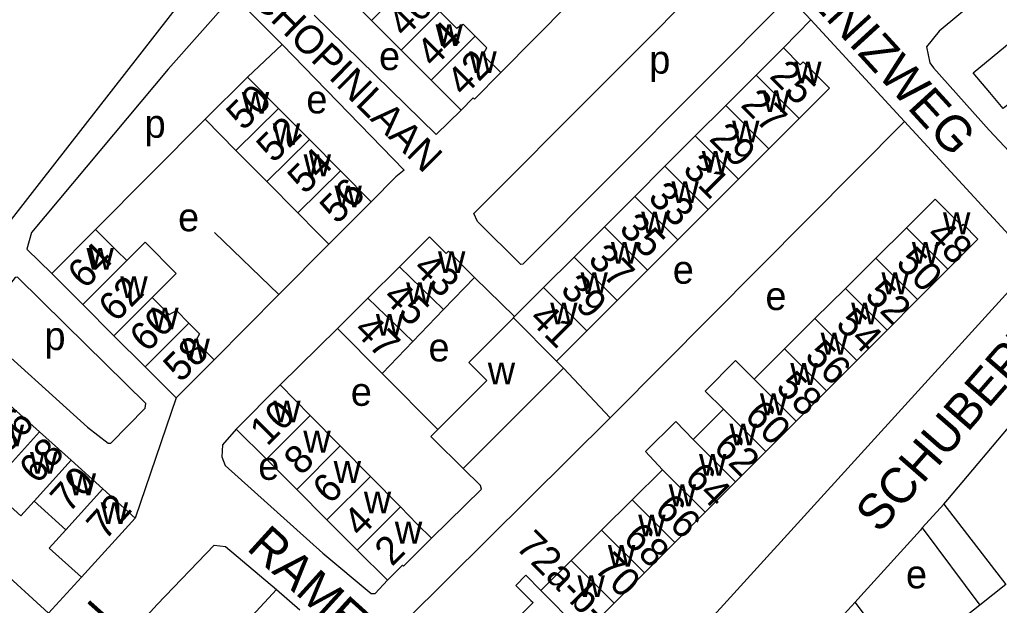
# Model space of a CAD drawing. Extents: x 159045 to 160918, y 380454 to 382516.
# Drawn here: x 159519.6 to 159658, y 381804.1 to 381886.8 of the extents above; entities that cross this region are included whole.
import ezdxf

# ---------------------------------------------------------------- set-up
doc = ezdxf.new("R2010")
doc.units = 0
for name, color, linetype in [('BLT_Basislijn', 7, 'Continuous'), ('BLT_Bebouwing', 7, 'Continuous'), ('BLT_Centroide', 7, 'Continuous'), ('BLT_Huisnummer', 7, 'Continuous'), ('BLT_Huisnummer_ tussenligend', 7, 'Continuous'), ('BLT_Huisnummer_reeks', 7, 'Continuous'), ('BLT_Onderverdeling_panden', 7, 'Continuous'), ('BLT_Straatnaam', 7, 'Continuous'), ('BLT_Straatnaam_verkleind', 7, 'Continuous')]:
    doc.layers.add(name, color=color, linetype=linetype)

msp = doc.modelspace()

# ---------------------------------------------------------------- linework, layer by layer
at = {"layer": 'BLT_Basislijn'}
for p, q in [((159631.34, 381886.81), (159628.29, 381890.11)), ((159587.58, 381879.35), (159597.19, 381889.05)), ((159627.48, 381882.85), (159631.34, 381886.81)), ((159644.57, 381872.44), (159631.34, 381886.81)), ((159556.7, 381883.3), (159551.82, 381878.71)), ((159545.83, 381872.77), (159530.37, 381857.19)), ((159556.25, 381848.03), (159547.18, 381856.77)), ((159556.25, 381848.03), (159563.28, 381855.14)), ((159583.86, 381850.43), (159589.52, 381844.89)), ((159547.1, 381838.78), (159556.25, 381848.03)), ((159556.44, 381835.24), (159564.51, 381843.2)), ((159596.45, 381837.61), (159603.01, 381830.59)), ((159570.83, 381836.86), (159578.69, 381828.95)), ((159541.75, 381833.42), (159535.95, 381816.45)), ((159647.09, 381815.05), (159650.13, 381818.42)), ((159650.13, 381818.42), (159658.86, 381807.04)), ((159647.09, 381815.05), (159655.21, 381804.14)), ((159513.46, 381812.35), (159523.74, 381802.99)), ((159528.39, 381808.1), (159523.74, 381802.99)), ((159555.91, 381806.36), (159559.19, 381803.48)), ((159637.61, 381804.56), (159634.52, 381801.16)), ((159644.4, 381795.56), (159637.61, 381804.56))]:
    msp.add_line(p, q, dxfattribs=at)
for points in [[(159671.87, 381915.68), (159677.46, 381909.03), (159676.79, 381907.98), (159673.6, 381905.32), (159649.48, 381885.21), (159647.67, 381882.98), (159648.15, 381880.73), (159648.65, 381880.03), (159656.52, 381871.2), (159665.8, 381861.36), (159667.35, 381860.48), (159668.8, 381860.27), (159671.09, 381861.15), (159710.49, 381901.86), (159730.69, 381922.64), (159732.46, 381924.74), (159732.71, 381927.22), (159731.89, 381928.43)], [(159531.44, 381910.25), (159541.64, 381900.41), (159542.72, 381899.11), (159542.72, 381889.82), (159522.41, 381863.71)], [(159628.29, 381890.11), (159590.71, 381852.28), (159590.42, 381852.23), (159584.27, 381858.32), (159583.75, 381859.44), (159619.87, 381895.69), (159620.88, 381896.42), (159622.32, 381896.52), (159628.29, 381890.11)], [(159556.7, 381883.3), (159550.19, 381889.89), (159549.56, 381889.98), (159540.63, 381879.85), (159521.32, 381856.75), (159520.65, 381854.44), (159524.17, 381850.99)], [(159581.97, 381874.07), (159578.45, 381870.61), (159561.21, 381887.45)], [(159556.7, 381883.3), (159573.94, 381865.59), (159572.75, 381864.63), (159569.29, 381861.09)], [(159644.57, 381872.44), (159660.96, 381854.63), (159661.66, 381853.63), (159661.82, 381852.68), (159661.18, 381850.54), (159599.18, 381782.35), (159598.21, 381781.87), (159596.31, 381781.68), (159595.12, 381782.25), (159574.14, 381801.25), (159574.2, 381802.01), (159603.01, 381830.59)], [(159603.01, 381830.59), (159603.52, 381831.1), (159644.57, 381872.44)], [(159522.41, 381863.71), (159472.38, 381799.37)], [(159526.08, 381843.82), (159519.34, 381850.45), (159519.02, 381850.4), (159513.78, 381843.71), (159513.9, 381843.1), (159529.21, 381829.29), (159532.16, 381827.01), (159532.54, 381827.01), (159537.36, 381831.96), (159537.45, 381832.64), (159526.08, 381843.82)], [(159650.13, 381818.42), (159650.71, 381819.07), (159660.55, 381830.73), (159662.87, 381831.27), (159663.98, 381831.15), (159676.84, 381819.54), (159684.1, 381812.42)], [(159550.22, 381829.02), (159548.3, 381826.78), (159548.2, 381825.08), (159548.68, 381823.88), (159562.44, 381811.5), (159569.26, 381805.8), (159569.83, 381805.78), (159571.59, 381807.65)], [(159577.79, 381813.58), (159584.85, 381820.51), (159584.73, 381821.06), (159582.28, 381823.44)], [(159647.09, 381815.05), (159646.82, 381814.74), (159638.42, 381805.46), (159637.61, 381804.56)], [(159512.29, 381774.89), (159539.04, 381804.23), (159547.11, 381812.6), (159548.72, 381812.44), (159555.91, 381806.36)], [(159555.91, 381806.36), (159520.46, 381767.98), (159519.92, 381768.08), (159515.83, 381771.39), (159512.29, 381774.89)]]:
    msp.add_lwpolyline(points, dxfattribs=at)
at = {"layer": 'BLT_Bebouwing'}
for p, q in [((159564.78, 381891.24), (159569.31, 381886.71)), ((159569.31, 381886.71), (159573.52, 381882.51)), ((159623.61, 381878.97), (159627.48, 381882.85)), ((159573.52, 381882.51), (159577.74, 381878.3)), ((159545.83, 381872.77), (159551.82, 381878.71)), ((159551.82, 381878.71), (159556.19, 381874.3)), ((159619.33, 381874.69), (159623.61, 381878.97)), ((159577.74, 381878.3), (159581.97, 381874.07)), ((159615.04, 381870.41), (159619.33, 381874.69)), ((159556.19, 381874.3), (159560.56, 381869.9)), ((159550.19, 381868.36), (159545.83, 381872.77)), ((159629.71, 381872.87), (159625.43, 381868.59)), ((159610.76, 381866.12), (159615.04, 381870.41)), ((159560.56, 381869.9), (159564.93, 381865.49)), ((159554.56, 381863.96), (159550.19, 381868.36)), ((159625.43, 381868.59), (159621.14, 381864.3)), ((159564.93, 381865.49), (159569.29, 381861.09)), ((159606.48, 381861.84), (159610.76, 381866.12)), ((159558.92, 381859.55), (159554.56, 381863.96)), ((159621.14, 381864.3), (159616.86, 381860.02)), ((159569.29, 381861.09), (159563.28, 381855.14)), ((159602.2, 381857.56), (159606.48, 381861.84)), ((159616.86, 381860.02), (159612.58, 381855.74)), ((159524.17, 381850.99), (159530.37, 381857.19)), ((159597.92, 381853.28), (159602.2, 381857.56)), ((159644.84, 381857.41), (159640.54, 381853.14)), ((159612.58, 381855.74), (159608.3, 381851.46)), ((159593.63, 381848.99), (159597.92, 381853.28)), ((159640.54, 381853.14), (159636.23, 381848.88)), ((159528.56, 381846.59), (159524.17, 381850.99)), ((159573.26, 381851.92), (159568.82, 381847.49)), ((159608.3, 381851.46), (159604.02, 381847.18)), ((159646.4, 381847.29), (159650.68, 381851.58)), ((159579.51, 381845.91), (159583.86, 381850.43)), ((159589.52, 381844.89), (159593.63, 381848.99)), ((159636.23, 381848.88), (159631.93, 381844.61)), ((159568.82, 381847.49), (159564.51, 381843.2)), ((159604.02, 381847.18), (159599.73, 381842.89)), ((159642.12, 381843), (159646.4, 381847.29)), ((159532.96, 381842.2), (159528.56, 381846.59)), ((159575.17, 381841.39), (159579.51, 381845.91)), ((159589.35, 381844.71), (159589.52, 381844.89)), ((159631.93, 381844.61), (159627.63, 381840.34)), ((159564.51, 381843.2), (159570.83, 381836.86)), ((159599.73, 381842.89), (159595.45, 381838.61)), ((159637.84, 381838.71), (159642.12, 381843)), ((159537.35, 381837.81), (159532.96, 381842.2)), ((159570.83, 381836.86), (159575.17, 381841.39)), ((159627.63, 381840.34), (159623.33, 381836.07)), ((159547.1, 381838.78), (159541.75, 381833.42)), ((159595.45, 381838.61), (159596.45, 381837.61)), ((159633.55, 381834.42), (159637.84, 381838.71)), ((159541.75, 381833.42), (159537.35, 381837.81)), ((159596.45, 381837.61), (159582.28, 381823.44)), ((159550.22, 381829.02), (159556.44, 381835.24)), ((159556.44, 381835.24), (159560.68, 381830.93)), ((159629.27, 381830.14), (159633.55, 381834.42)), ((159517.84, 381832.77), (159522.43, 381828.64)), ((159619.02, 381831.8), (159614.72, 381827.54)), ((159560.68, 381830.93), (159564.92, 381826.62)), ((159554.49, 381824.74), (159550.22, 381829.02)), ((159624.99, 381825.85), (159629.27, 381830.14)), ((159522.43, 381828.64), (159526.9, 381824.61)), ((159578.07, 381827.59), (159582.28, 381823.44)), ((159564.92, 381826.62), (159569.16, 381822.32)), ((159558.76, 381820.47), (159554.49, 381824.74)), ((159620.71, 381821.56), (159624.99, 381825.85)), ((159526.9, 381824.61), (159531.37, 381820.58)), ((159610.42, 381823.27), (159606.12, 381819)), ((159569.16, 381822.32), (159573.4, 381818.01)), ((159531.37, 381820.58), (159535.95, 381816.45)), ((159616.43, 381817.27), (159620.71, 381821.56)), ((159563.04, 381816.2), (159558.76, 381820.47)), ((159526.16, 381814.8), (159521.69, 381818.83)), ((159606.12, 381819), (159601.81, 381814.73)), ((159535.95, 381816.45), (159528.39, 381808.1)), ((159612.14, 381812.98), (159616.43, 381817.27)), ((159567.31, 381811.92), (159563.04, 381816.2)), ((159601.81, 381814.73), (159597.51, 381810.47)), ((159607.86, 381808.7), (159612.14, 381812.98)), ((159571.59, 381807.65), (159567.31, 381811.92)), ((159597.51, 381810.47), (159593.21, 381806.2)), ((159603.58, 381804.41), (159607.86, 381808.7)), ((159658.86, 381807.04), (159655.21, 381804.14)), ((159599.3, 381800.12), (159603.58, 381804.41)), ((159655.21, 381804.14), (159651.63, 381801.3))]:
    msp.add_line(p, q, dxfattribs=at)
for points in [[(159578.99, 381887.98), (159581.32, 381885.65), (159582.28, 381886.19), (159583.95, 381884.52)], [(159587.58, 381879.35), (159585.05, 381881.87), (159585.62, 381882.85), (159583.95, 381884.52)], [(159627.48, 381882.85), (159629.86, 381880.47), (159630.27, 381880.87), (159633.99, 381877.15), (159629.71, 381872.87)], [(159667.17, 381874.66), (159662.55, 381870.82), (159659.21, 381874.85), (159658.49, 381874.26), (159656.61, 381876.52), (159654.29, 381879.31), (159659.62, 381883.75), (159661.81, 381881.12)], [(159581.97, 381874.07), (159583.69, 381875.79), (159583.86, 381875.62), (159587.58, 381879.35)], [(159650.68, 381851.58), (159654.95, 381855.85), (159652.86, 381857.94), (159652.65, 381857.73), (159648.91, 381861.47), (159646.83, 381859.39), (159644.84, 381857.41)], [(159563.28, 381855.14), (159561.62, 381856.81), (159558.92, 381859.55)], [(159530.37, 381857.19), (159533.32, 381854.24), (159534.76, 381852.8)], [(159534.76, 381852.8), (159537.35, 381855.39), (159541.75, 381851), (159538.36, 381847.61)], [(159583.86, 381850.43), (159580.18, 381854.12), (159579.86, 381853.8), (159577.51, 381856.16), (159573.26, 381851.92)], [(159538.36, 381847.61), (159540.76, 381845.21), (159541.77, 381845.74), (159543.52, 381843.99)], [(159578.69, 381828.95), (159585.62, 381835.88), (159583.07, 381838.43), (159589.35, 381844.71)], [(159543.52, 381843.99), (159545.05, 381842.46), (159544.46, 381841.42), (159547.1, 381838.78)], [(159623.33, 381836.07), (159620.73, 381838.69), (159616.44, 381834.37), (159619.02, 381831.8)], [(159578.07, 381827.59), (159577.7, 381827.96), (159578.69, 381828.95)], [(159614.72, 381827.54), (159612.27, 381830.08), (159608.03, 381825.84), (159610.42, 381823.27)], [(159521.69, 381818.83), (159519.82, 381816.75), (159515.35, 381820.77)], [(159573.4, 381818.01), (159575.79, 381815.58), (159577.79, 381813.58)], [(159528.39, 381808.1), (159523.83, 381812.21), (159526.16, 381814.8)], [(159577.79, 381813.58), (159577.39, 381813.19), (159573.86, 381809.65), (159573.72, 381809.79), (159571.59, 381807.65)], [(159593.21, 381806.2), (159591.12, 381808.36), (159589.7, 381806.92), (159591.8, 381804.82), (159592.13, 381804.5), (159589.56, 381801.93)]]:
    msp.add_lwpolyline(points, dxfattribs=at)
at = {"layer": 'BLT_Onderverdeling_panden'}
for p, q in [((159575.55, 381892.96), (159569.31, 381886.71)), ((159578.99, 381887.98), (159573.52, 381882.51)), ((159583.95, 381884.52), (159577.74, 381878.3)), ((159629.71, 381872.87), (159623.61, 381878.97)), ((159625.43, 381868.59), (159619.33, 381874.69)), ((159550.19, 381868.36), (159556.19, 381874.3)), ((159621.14, 381864.3), (159615.04, 381870.41)), ((159554.56, 381863.96), (159560.56, 381869.9)), ((159558.92, 381859.55), (159564.93, 381865.49)), ((159616.86, 381860.02), (159610.76, 381866.12)), ((159612.58, 381855.74), (159606.48, 381861.84)), ((159608.3, 381851.46), (159602.2, 381857.56)), ((159650.68, 381851.58), (159644.84, 381857.41)), ((159528.56, 381846.59), (159534.76, 381852.8)), ((159604.02, 381847.18), (159597.92, 381853.28)), ((159646.4, 381847.29), (159640.54, 381853.14)), ((159579.51, 381845.91), (159573.26, 381851.92)), ((159599.73, 381842.89), (159593.63, 381848.99)), ((159642.12, 381843), (159636.23, 381848.88)), ((159532.96, 381842.2), (159538.36, 381847.61)), ((159575.17, 381841.39), (159568.82, 381847.49)), ((159595.45, 381838.61), (159589.35, 381844.71)), ((159637.84, 381838.71), (159631.93, 381844.61)), ((159537.35, 381837.81), (159543.52, 381843.99)), ((159633.55, 381834.42), (159627.63, 381840.34)), ((159629.27, 381830.14), (159623.33, 381836.07)), ((159624.99, 381825.85), (159619.02, 381831.8)), ((159554.49, 381824.74), (159560.68, 381830.93)), ((159515.35, 381820.77), (159522.43, 381828.64)), ((159620.71, 381821.56), (159614.72, 381827.54)), ((159558.76, 381820.47), (159564.92, 381826.62)), ((159521.69, 381818.83), (159526.9, 381824.61)), ((159616.43, 381817.27), (159610.42, 381823.27)), ((159563.04, 381816.2), (159569.16, 381822.32)), ((159526.16, 381814.8), (159531.37, 381820.58)), ((159567.31, 381811.92), (159573.4, 381818.01)), ((159612.14, 381812.98), (159606.12, 381819)), ((159607.86, 381808.7), (159601.81, 381814.73)), ((159603.58, 381804.41), (159597.51, 381810.47)), ((159599.3, 381800.12), (159593.21, 381806.2))]:
    msp.add_line(p, q, dxfattribs=at)

# ---------------------------------------------------------------- texts
at = {"layer": 'BLT_Centroide'}
for s, p in [('w', (159578.36, 381883.12)), ('e', (159570.39, 381879.71)), ('w', (159583.13, 381879.28)), ('p', (159608.54, 381879.21)), ('w', (159629, 381877.84)), ('w', (159551.01, 381873.53)), ('e', (159560.13, 381873.59)), ('w', (159624.52, 381873.78)), ('p', (159537.29, 381870.15)), ('w', (159555.38, 381869.12)), ('w', (159620.23, 381869.5)), ('w', (159559.74, 381864.72)), ('w', (159615.95, 381865.22)), ('w', (159611.67, 381860.94)), ('w', (159564.1, 381860.31)), ('e', (159542.02, 381856.94)), ('w', (159607.39, 381856.66)), ('w', (159650.01, 381856.53)), ('w', (159603.11, 381852.38)), ('w', (159645.61, 381852.36)), ('w', (159529.08, 381851.5)), ('w', (159578.71, 381851.03)), ('e', (159611.86, 381849.54)), ('w', (159598.83, 381848.09)), ('w', (159641.32, 381848.06)), ('w', (159533.86, 381847.5)), ('w', (159574.21, 381846.66)), ('e', (159624.94, 381845.82)), ('w', (159594.55, 381843.81)), ('w', (159637.04, 381843.78)), ('w', (159538.23, 381843.09)), ('w', (159569.94, 381842.19)), ('p', (159523.15, 381840.17)), ('w', (159542.64, 381838.72)), ('e', (159577.37, 381838.56)), ('w', (159632.74, 381839.53)), ('w', (159585.74, 381835.33)), ('w', (159628.45, 381835.25)), ('e', (159566.4, 381832.29)), ('w', (159555.45, 381829.97)), ('w', (159624.16, 381830.97)), ('w', (159516.41, 381826.55)), ('w', (159619.87, 381826.69)), ('w', (159559.7, 381825.69)), ('w', (159521.12, 381822.69)), ('e', (159553.34, 381821.84)), ('w', (159615.57, 381822.41)), ('w', (159563.98, 381821.41)), ('w', (159526.56, 381819.67)), ('w', (159611.28, 381818.12)), ('w', (159568.24, 381817.12)), ('w', (159531.09, 381815.61)), ('w', (159606.98, 381813.86)), ('w', (159572.62, 381812.84)), ('w', (159602.7, 381809.56)), ('e', (159644.78, 381806.52)), ('w', (159598.4, 381805.28))]:
    msp.add_text(s, height=4, dxfattribs=at).set_placement(p)
at = {"layer": 'BLT_Huisnummer'}
for s, rotation, p in [('42', 45.0462, (159582.34, 381875.84)), ('25', 315.0047, (159625.37, 381878.72)), ('50', 44.7024, (159551.24, 381871.02)), ('29', 315.0047, (159616.86, 381869.89)), ('56', 44.7557, (159564.45, 381857.81)), ('33', 315.0047, (159608.2, 381861.54)), ('48', 315.0393, (159647.46, 381856.2)), ('64', 45.0231, (159528.87, 381848.64)), ('37', 315, (159599.73, 381852.76)), ('43', 316.1491, (159575.02, 381851.5)), ('52', 315.039, (159638.8, 381847.72)), ('41', 315, (159591.39, 381844.41)), ('47', 314.9094, (159566.63, 381842.81)), ('58', 45.0267, (159542.38, 381835.46)), ('56', 315.0436, (159630.32, 381839.17)), ('10', 45.0046, (159554.59, 381826.47)), ('66', 47.975, (159517.93, 381825.33)), ('60', 315.0335, (159621.81, 381830.66)), ('64', 315.0428, (159613.35, 381821.87)), ('6', 45.0047, (159563.45, 381818.24)), ('72', 47.9799, (159531.7, 381813.16)), ('68', 315.0427, (159604.67, 381813.39)), ('2', 45, (159572.2, 381809.51))]:
    msp.add_text(s, height=4, rotation=rotation, dxfattribs=at).set_placement(p)
at = {"layer": 'BLT_Huisnummer_ tussenligend'}
for s, rotation, p in [('46', 45.0462, (159574.02, 381884.15)), ('44', 45.0462, (159578.09, 381879.9)), ('27', 315.0047, (159621.29, 381874.66)), ('52', 44.7024, (159555.5, 381866.45)), ('54', 44.7024, (159559.9, 381862.03)), ('31', 315.0047, (159613.11, 381865.5)), ('35', 315.0047, (159604.12, 381857.12)), ('50', 315.0393, (159643.21, 381852.31)), ('62', 45.0267, (159533.22, 381843.95)), ('39', 315, (159595.84, 381848.52)), ('45', 316.1491, (159570.77, 381847.43)), ('60', 45.0267, (159537.62, 381839.69)), ('54', 315.039, (159634.71, 381843.66)), ('58', 315.0436, (159626.25, 381834.75)), ('68', 47.975, (159522.18, 381821.09)), ('62', 315.0335, (159617.41, 381826.24)), ('8', 45.0047, (159559.39, 381822.31)), ('70', 47.975, (159526.58, 381817.02)), ('66', 315.0428, (159609.11, 381817.46)), ('4', 45, (159567.78, 381813.57)), ('70', 315.0427, (159600.6, 381809.16))]:
    msp.add_text(s, height=4, rotation=rotation, dxfattribs=at).set_placement(p)
at = {"layer": 'BLT_Huisnummer_reeks'}
msp.add_text('72a-b-c', height=4, rotation=315.0424, dxfattribs=at).set_placement((159589.52, 381812.26))
at = {"layer": 'BLT_Straatnaam'}
for s, rotation, p in [('ALBENIZWEG', 312.4447, (159621.78, 381899.58)), ('SCHUBERTLAAN', 48.9522, (159641.04, 381814.15)), ('RAMEAUSTRAAT', 317.7925, (159551.54, 381812.06)), ('CHOPINLAAN', 48.1941, (159504.7, 381769.49))]:
    msp.add_text(s, height=5, rotation=rotation, dxfattribs=at).set_placement(p)
at = {"layer": 'BLT_Straatnaam_verkleind'}
msp.add_text('CHOPINLAAN', height=4, rotation=315.1769, dxfattribs=at).set_placement((159552.16, 381889.5))

doc.saveas('drawing.dxf')
